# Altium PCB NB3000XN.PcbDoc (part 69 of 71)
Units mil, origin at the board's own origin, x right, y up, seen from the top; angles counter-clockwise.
Board outline 9527.56 x 6929.77 mil, 6 copper layers (Top Layer, GND+SHIELD, MidLayer1, MidLayer2, P2 - 3V3+5V0, Bottom Layer), stack 62.375 mil thick; 832 components, 1027 nets, 4655 pads, 4981 vias.
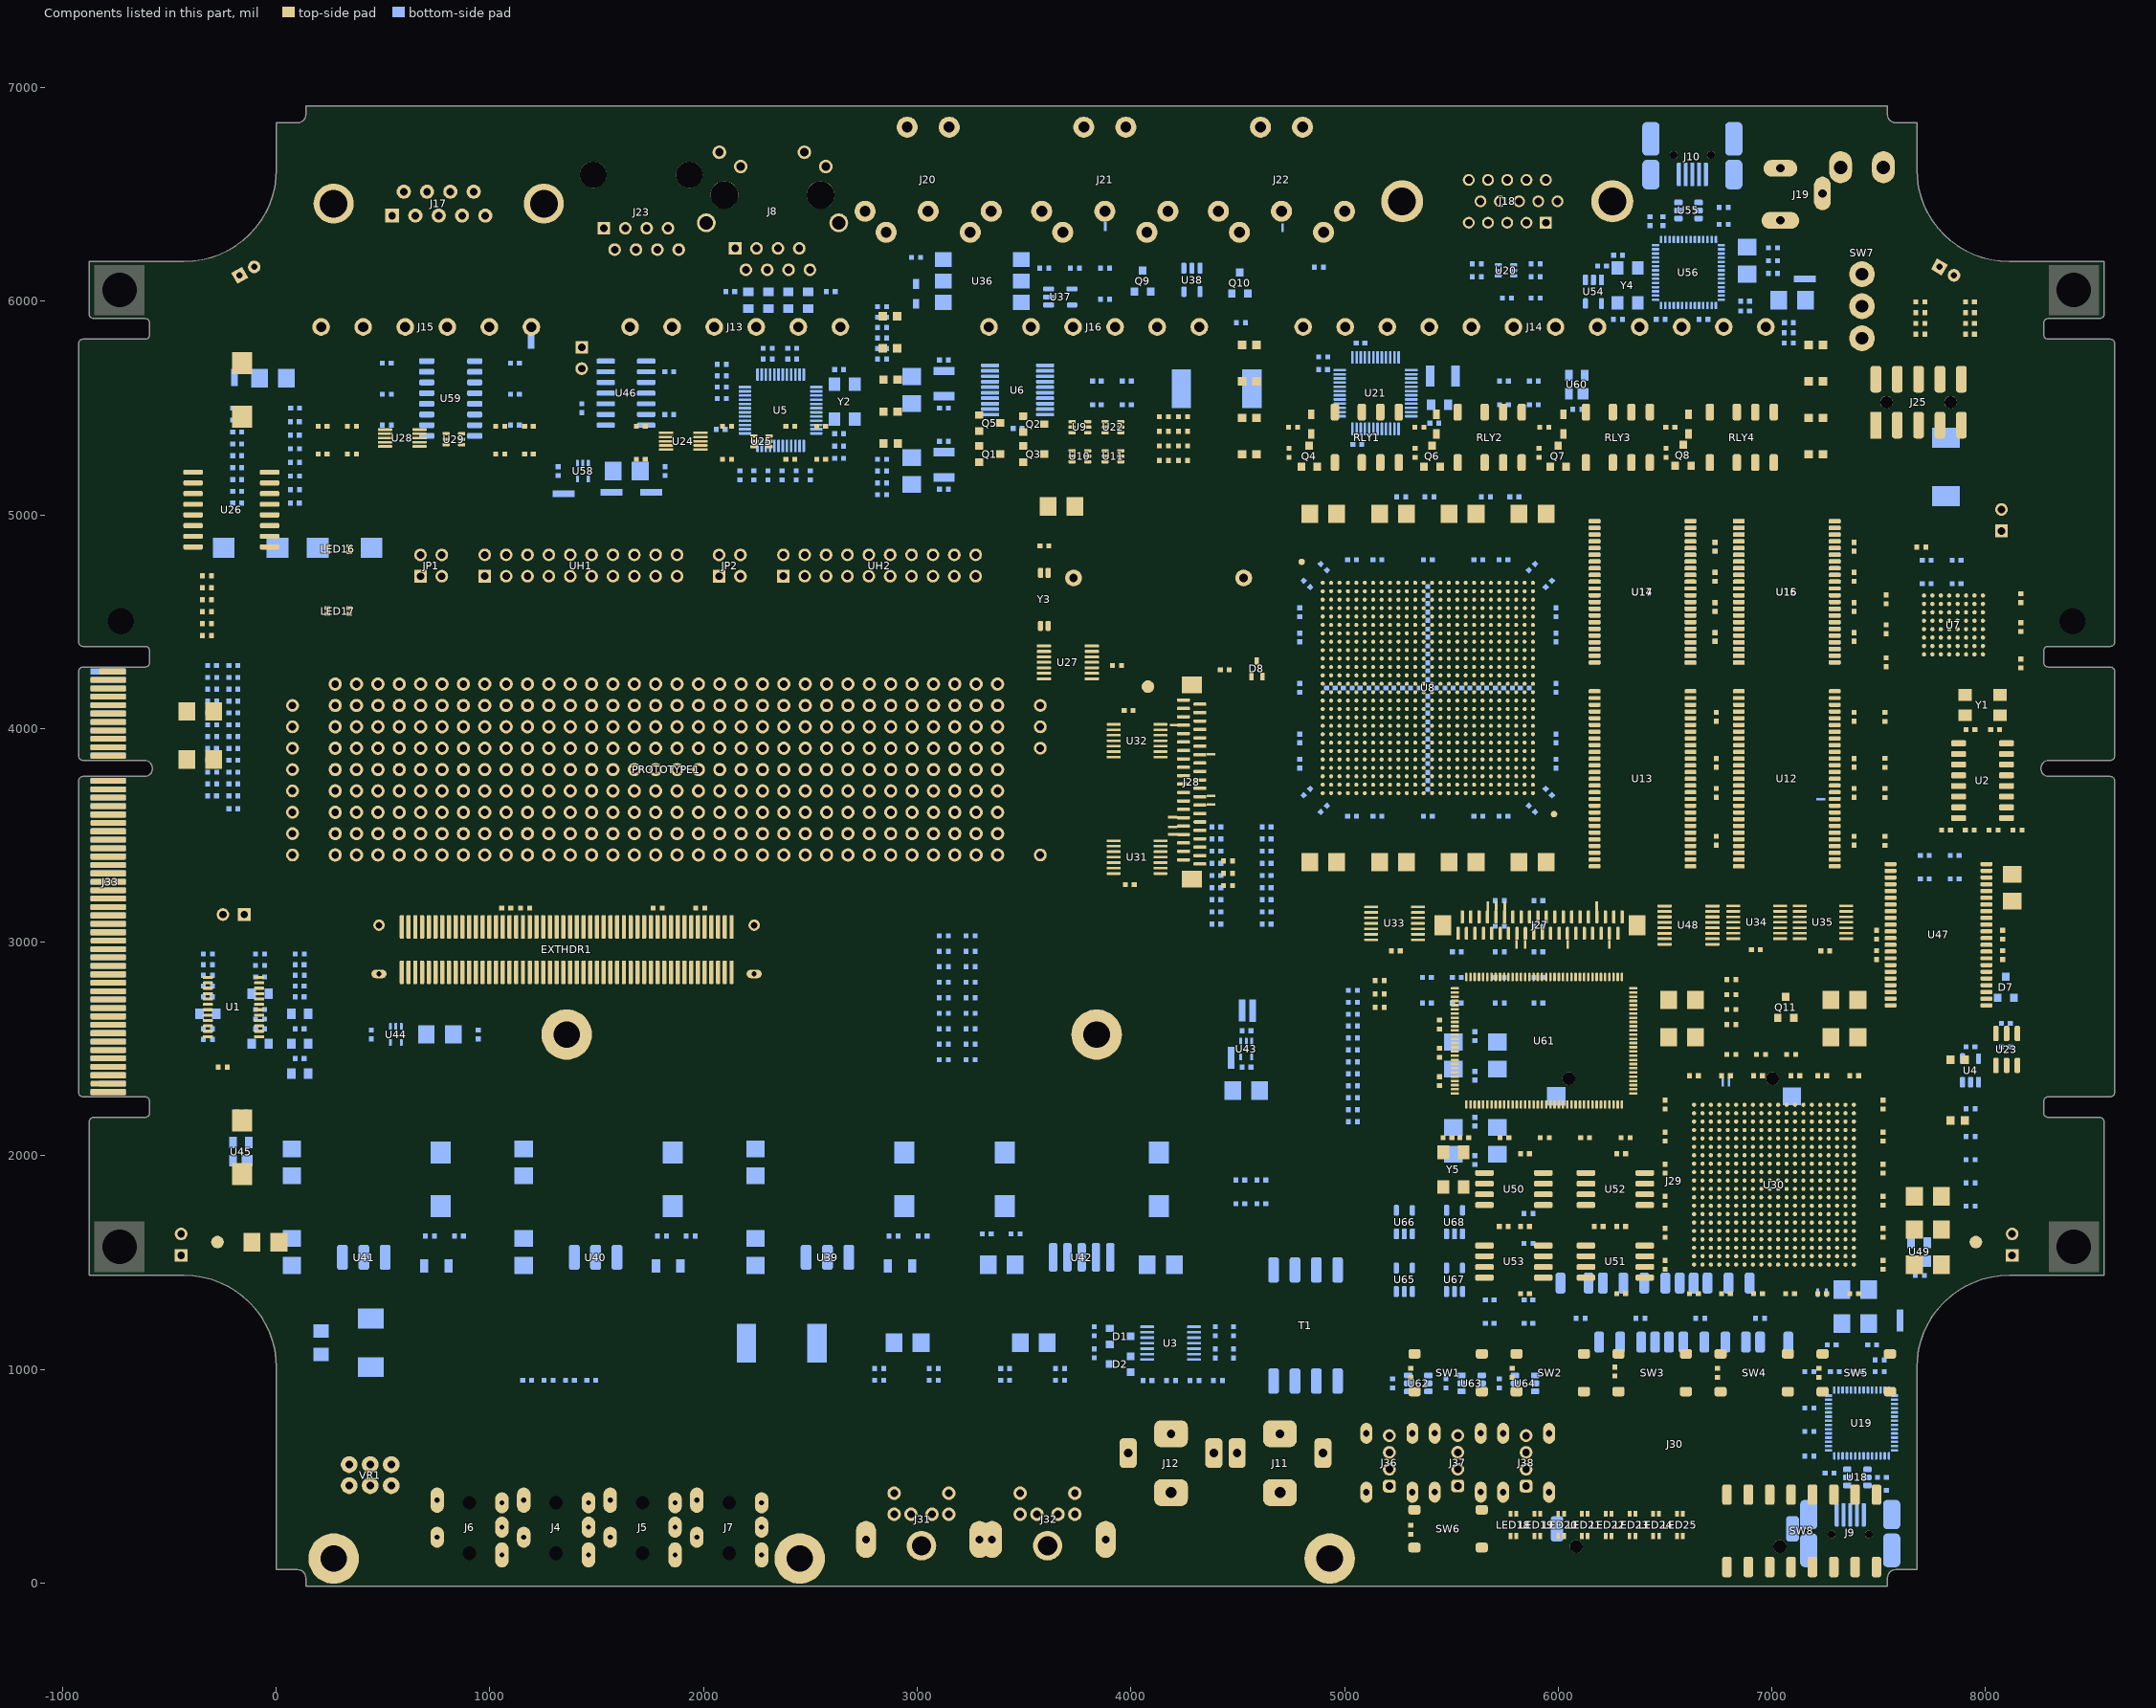
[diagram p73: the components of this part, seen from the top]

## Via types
v1: diameter 23, hole 11.81, Top Layer to Bottom Layer, 3672 vias
v2: diameter 26, hole 11.81, Top Layer to Bottom Layer, 461 vias
v3: diameter 19, hole 11.81, Top Layer to Bottom Layer, tented both sides, 396 vias
v4: diameter 23.62, hole 11.81, Top Layer to Bottom Layer, 288 vias
v5: diameter 20, hole 11.81, Top Layer to Bottom Layer, 91 vias
v6: diameter 23, hole 11.81, Top Layer to Bottom Layer, tented both sides, 50 vias
v7: diameter 31, hole 11.81, Top Layer to Bottom Layer, 15 vias
v8: diameter 27.56, hole 11.81, Top Layer to Bottom Layer, tented both sides, 4 vias
v9: diameter 29, hole 11.81, Top Layer to Bottom Layer, 3 vias
v10: diameter 21, hole 11.81, Top Layer to Bottom Layer, 1 vias

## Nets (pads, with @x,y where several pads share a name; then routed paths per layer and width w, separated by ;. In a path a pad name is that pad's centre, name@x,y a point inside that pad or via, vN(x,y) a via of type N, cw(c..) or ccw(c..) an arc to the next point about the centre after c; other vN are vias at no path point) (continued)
copper on no net: (continued)
  Top Layer w8: v2(6773.78,1550.04) 6793.46,1569.72 ; v2@6773.78,1559.04 ccw(c6773.78,1580.77) 6789.14,1565.4 ccw(c6804.51,1550.04) v2@6782.78,1550.04 ; v2(6773.78,1825.63) 6793.46,1845.31 ; v2@6773.78,1834.63 ccw(c6773.78,1856.36) 6789.14,1840.99 ccw(c6804.51,1825.63) v2@6782.78,1825.63 ; 6787.62,1569.72 cw(c6773.52,1569.72) 6783.49,1559.75 cw(c6793.46,1549.78) 6793.46,1563.88 ; 6787.62,1845.31 cw(c6773.52,1845.31) 6783.49,1835.34 cw(c6793.46,1825.37) 6793.46,1839.47 ; v2(6813.15,1471.3) 6832.83,1490.98 ; v2@6813.15,1480.3 ccw(c6813.15,1502.03) 6828.51,1486.66 ccw(c6843.88,1471.3) v2@6822.15,1471.3 ; v2(6813.15,1510.67) 6832.83,1530.35 ; v2@6813.15,1519.67 ccw(c6813.15,1541.4) 6828.51,1526.03 ccw(c6843.88,1510.67) v2@6822.15,1510.67 ; v2(6813.15,1550.04) 6832.83,1569.72 ; v2@6813.15,1559.04 ccw(c6813.15,1580.77) 6828.51,1565.4 ccw(c6843.88,1550.04) v2@6822.15,1550.04 ; v2(6813.15,1589.41) 6832.83,1609.09 ; v2@6813.15,1598.41 ccw(c6813.15,1620.14) 6828.51,1604.77 ccw(c6843.88,1589.41) v2@6822.15,1589.41 ; v2(6813.15,1628.78) 6832.83,1648.46 ; v2@6813.15,1637.78 ccw(c6813.15,1659.51) 6828.51,1644.14 ccw(c6843.88,1628.78) v2@6822.15,1628.78 ; v2(6813.15,1707.52) 6832.83,1727.2 ; v2@6813.15,1716.52 ccw(c6813.15,1738.25) 6828.51,1722.88 ccw(c6843.88,1707.52) v2@6822.15,1707.52 ; v2@6813.15,1895.37 cw(c6813.15,1873.64) 6828.51,1889.01 cw(c6843.88,1904.37) v2@6822.15,1904.37 ; v2(6813.15,1904.37) 6832.83,1884.68 ; v2@6813.15,1974.11 cw(c6813.15,1952.38) 6828.51,1967.75 cw(c6843.88,1983.11) v2@6822.15,1983.11 ; v2(6813.15,1983.11) 6832.83,1963.43 ; 6826.99,1490.98 cw(c6812.89,1490.98) 6822.86,1481.01 cw(c6832.83,1471.04) 6832.83,1485.14 ; 6826.99,1530.35 cw(c6812.89,1530.35) 6822.86,1520.38 cw(c6832.83,1510.41) 6832.83,1524.51 ; 6826.99,1569.72 cw(c6812.89,1569.72) 6822.86,1559.75 cw(c6832.83,1549.78) 6832.83,1563.88 ; 6826.99,1609.09 cw(c6812.89,1609.09) 6822.86,1599.12 cw(c6832.83,1589.15) 6832.83,1603.25 ; 6826.99,1648.46 cw(c6812.89,1648.46) 6822.86,1638.49 cw(c6832.83,1628.52) 6832.83,1642.62 ; 6826.99,1727.2 cw(c6812.89,1727.2) 6822.86,1717.23 cw(c6832.83,1707.26) 6832.83,1721.36 ; 6826.99,1884.68 ccw(c6812.89,1884.68) 6822.86,1894.66 ccw(c6832.83,1904.63) 6832.83,1890.53 ; 6826.99,1963.43 ccw(c6812.89,1963.43) 6822.86,1973.4 ccw(c6832.83,1983.37) 6832.83,1969.27 ; v2(6852.52,1550.04) 6872.2,1569.72 ; v2@6852.52,1559.04 ccw(c6852.52,1580.77) 6867.88,1565.4 ccw(c6883.25,1550.04) v2@6861.52,1550.04 ; v2(6852.52,1589.41) 6872.2,1609.09 ; v2@6852.52,1598.41 ccw(c6852.52,1620.14) 6867.88,1604.77 ccw(c6883.25,1589.41) v2@6861.52,1589.41 ; v2(6852.52,1628.78) 6872.2,1648.46 ; v2@6852.52,1637.78 ccw(c6852.52,1659.51) 6867.88,1644.14 ccw(c6883.25,1628.78) v2@6861.52,1628.78 ; v2(6852.52,1668.15) 6872.2,1687.83 ; v2@6852.52,1677.15 ccw(c6852.52,1698.88) 6867.88,1683.51 ccw(c6883.25,1668.15) v2@6861.52,1668.15 ; v2(6852.52,1707.52) 6872.2,1727.2 ; v2@6852.52,1716.52 ccw(c6852.52,1738.25) 6867.88,1722.88 ccw(c6883.25,1707.52) v2@6861.52,1707.52 ; v2(6852.52,1746.89) 6872.2,1766.57 ; v2@6852.52,1755.89 ccw(c6852.52,1777.62) 6867.88,1762.25 ccw(c6883.25,1746.89) v2@6861.52,1746.89 ; v2(6852.52,1786.26) 6872.2,1805.94 ; v2@6852.52,1795.26 ccw(c6852.52,1816.99) 6867.88,1801.62 ccw(c6883.25,1786.26) v2@6861.52,1786.26 ; v2(6852.52,1825.63) 6872.2,1845.31 ; v2@6852.52,1834.63 ccw(c6852.52,1856.36) 6867.88,1840.99 ccw(c6883.25,1825.63) v2@6861.52,1825.63 ; v2@6852.52,1895.37 cw(c6852.52,1873.64) 6867.88,1889.01 cw(c6883.25,1904.37) v2@6861.52,1904.37 ; v2(6852.52,1904.37) 6872.2,1884.68 ; v2@6852.52,1934.74 cw(c6852.52,1913.01) 6867.88,1928.38 cw(c6883.25,1943.74) v2@6861.52,1943.74 ; v2(6852.52,1943.74) 6872.2,1924.06 ; v2@6852.52,1974.11 cw(c6852.52,1952.38) 6867.88,1967.75 cw(c6883.25,1983.11) v2@6861.52,1983.11 ; v2(6852.52,1983.11) 6872.2,1963.43 ; v2@6852.52,2013.48 cw(c6852.52,1991.75) 6867.88,2007.12 cw(c6883.25,2022.48) v2@6861.52,2022.48 ; v2(6852.52,2022.48) 6872.2,2002.8 ; v2@6852.52,2052.85 cw(c6852.52,2031.12) 6867.88,2046.49 cw(c6883.25,2061.85) v2@6861.52,2061.85 ; v2(6852.52,2061.85) 6872.2,2042.17 ; v2@6852.52,2092.22 cw(c6852.52,2070.49) 6867.88,2085.86 cw(c6883.25,2101.22) v2@6861.52,2101.22 ; v2(6852.52,2101.22) 6872.2,2081.54 ; 6866.36,1569.72 cw(c6852.26,1569.72) 6862.23,1559.75 cw(c6872.2,1549.78) 6872.2,1563.88 ; 6866.36,1609.09 cw(c6852.26,1609.09) 6862.23,1599.12 cw(c6872.2,1589.15) 6872.2,1603.25 ; 6866.36,1648.46 cw(c6852.26,1648.46) 6862.23,1638.49 cw(c6872.2,1628.52) 6872.2,1642.62 ; 6866.36,1687.83 cw(c6852.26,1687.83) 6862.23,1677.86 cw(c6872.2,1667.89) 6872.2,1681.99 ; 6866.36,1727.2 cw(c6852.26,1727.2) 6862.23,1717.23 cw(c6872.2,1707.26) 6872.2,1721.36 ; 6866.36,1766.57 cw(c6852.26,1766.57) 6862.23,1756.6 cw(c6872.2,1746.63) 6872.2,1760.73 ; 6866.36,1805.94 cw(c6852.26,1805.94) 6862.23,1795.97 cw(c6872.2,1786) 6872.2,1800.1 ; 6866.36,1845.31 cw(c6852.26,1845.31) 6862.23,1835.34 cw(c6872.2,1825.37) 6872.2,1839.47 ; 6866.36,1884.68 ccw(c6852.26,1884.68) 6862.23,1894.66 ccw(c6872.2,1904.63) 6872.2,1890.53 ; 6866.36,1924.06 ccw(c6852.26,1924.06) 6862.23,1934.03 ccw(c6872.2,1944) 6872.2,1929.9 ; 6866.36,1963.43 ccw(c6852.26,1963.43) 6862.23,1973.4 ccw(c6872.2,1983.37) 6872.2,1969.27 ; 6866.36,2002.8 ccw(c6852.26,2002.8) 6862.23,2012.77 ccw(c6872.2,2022.74) 6872.2,2008.64 ; 6866.36,2042.17 ccw(c6852.26,2042.17) 6862.23,2052.14 ccw(c6872.2,2062.11) 6872.2,2048.01 ; 6866.36,2081.54 ccw(c6852.26,2081.54) 6862.23,2091.51 ccw(c6872.2,2101.48) 6872.2,2087.38 ; v2(6891.89,1510.67) 6911.57,1530.35 ; v2@6891.89,1519.67 ccw(c6891.89,1541.4) 6907.25,1526.03 ccw(c6922.62,1510.67) v2@6900.89,1510.67 ; v2(6891.89,1550.04) 6911.57,1569.72 ; v2@6891.89,1559.04 ccw(c6891.89,1580.77) 6907.25,1565.4 ccw(c6922.62,1550.04) v2@6900.89,1550.04 ; v2(6891.89,1589.41) 6911.57,1609.09 ; v2@6891.89,1598.41 ccw(c6891.89,1620.14) 6907.25,1604.77 ccw(c6922.62,1589.41) v2@6900.89,1589.41 ; v2(6891.89,1668.15) 6911.57,1687.83 ; v2@6891.89,1677.15 ccw(c6891.89,1698.88) 6907.25,1683.51 ccw(c6922.62,1668.15) v2@6900.89,1668.15 ; v2(6891.89,1707.52) 6911.57,1727.2 ; v2@6891.89,1716.52 ccw(c6891.89,1738.25) 6907.25,1722.88 ccw(c6922.62,1707.52) v2@6900.89,1707.52 ; v2(6891.89,1786.26) 6911.57,1805.94 ; v2@6891.89,1795.26 ccw(c6891.89,1816.99) 6907.25,1801.62 ccw(c6922.62,1786.26) v2@6900.89,1786.26 ; v2@6891.89,1934.74 cw(c6891.89,1913.01) 6907.25,1928.38 cw(c6922.62,1943.74) v2@6900.89,1943.74 ; v2(6891.89,1943.74) 6911.57,1924.06 ; v2@6891.89,2013.48 cw(c6891.89,1991.75) 6907.25,2007.12 cw(c6922.62,2022.48) v2@6900.89,2022.48 ; v2(6891.89,2022.48) 6911.57,2002.8 ; v2@6891.89,2052.85 cw(c6891.89,2031.12) 6907.25,2046.49 cw(c6922.62,2061.85) v2@6900.89,2061.85 ; v2(6891.89,2061.85) 6911.57,2042.17 ; 6905.73,1530.35 cw(c6891.63,1530.35) 6901.6,1520.38 cw(c6911.57,1510.41) 6911.57,1524.51 ; 6905.73,1569.72 cw(c6891.63,1569.72) 6901.6,1559.75 cw(c6911.57,1549.78) 6911.57,1563.88 ; 6905.73,1609.09 cw(c6891.63,1609.09) 6901.6,1599.12 cw(c6911.57,1589.15) 6911.57,1603.25 ; 6905.73,1687.83 cw(c6891.63,1687.83) 6901.6,1677.86 cw(c6911.57,1667.89) 6911.57,1681.99 ; 6905.73,1727.2 cw(c6891.63,1727.2) 6901.6,1717.23 cw(c6911.57,1707.26) 6911.57,1721.36 ; 6905.73,1805.94 cw(c6891.63,1805.94) 6901.6,1795.97 cw(c6911.57,1786) 6911.57,1800.1 ; 6905.73,1924.06 ccw(c6891.63,1924.06) 6901.6,1934.03 ccw(c6911.57,1944) 6911.57,1929.9 ; 6905.73,2002.8 ccw(c6891.63,2002.8) 6901.6,2012.77 ccw(c6911.57,2022.74) 6911.57,2008.64 ; 6905.73,2042.17 ccw(c6891.63,2042.17) 6901.6,2052.14 ccw(c6911.57,2062.11) 6911.57,2048.01 ; v2(6931.26,1471.3) 6950.94,1490.98 ; v2@6931.26,1480.3 ccw(c6931.26,1502.03) 6946.62,1486.66 ccw(c6961.99,1471.3) v2@6940.26,1471.3 ; v2(6931.26,1510.67) 6950.94,1530.35 ; v2@6931.26,1519.67 ccw(c6931.26,1541.4) 6946.62,1526.03 ccw(c6961.99,1510.67) v2@6940.26,1510.67 ; v2(6931.26,1550.04) 6950.94,1569.72 ; v2@6931.26,1559.04 ccw(c6931.26,1580.77) 6946.62,1565.4 ccw(c6961.99,1550.04) v2@6940.26,1550.04 ; v2(6931.26,1589.41) 6950.94,1609.09 ; v2@6931.26,1598.41 ccw(c6931.26,1620.14) 6946.62,1604.77 ccw(c6961.99,1589.41) v2@6940.26,1589.41 ; v2(6931.26,1628.78) 6950.94,1648.46 ; v2@6931.26,1637.78 ccw(c6931.26,1659.51) 6946.62,1644.14 ccw(c6961.99,1628.78) v2@6940.26,1628.78 ; v2(6931.26,1668.15) 6950.94,1687.83 ; v2@6931.26,1677.15 ccw(c6931.26,1698.88) 6946.62,1683.51 ccw(c6961.99,1668.15) v2@6940.26,1668.15 ; v2(6931.26,1707.52) 6950.94,1727.2 ; v2@6931.26,1716.52 ccw(c6931.26,1738.25) 6946.62,1722.88 ccw(c6961.99,1707.52) v2@6940.26,1707.52 ; v2(6931.26,1746.89) 6950.94,1766.57 ; v2@6931.26,1755.89 ccw(c6931.26,1777.62) 6946.62,1762.25 ccw(c6961.99,1746.89) v2@6940.26,1746.89 ; v2@6931.26,1974.11 cw(c6931.26,1952.38) 6946.62,1967.75 cw(c6961.99,1983.11) v2@6940.26,1983.11 ; v2(6931.26,1983.11) 6950.94,1963.43 ; v2@6931.26,2013.48 cw(c6931.26,1991.75) 6946.62,2007.12 cw(c6961.99,2022.48) v2@6940.26,2022.48 ; v2(6931.26,2022.48) 6950.94,2002.8 ; v2@6931.26,2052.85 cw(c6931.26,2031.12) 6946.62,2046.49 cw(c6961.99,2061.85) v2@6940.26,2061.85 ; v2(6931.26,2061.85) 6950.94,2042.17 ; 6945.1,1490.98 cw(c6931,1490.98) 6940.97,1481.01 cw(c6950.94,1471.04) 6950.94,1485.14 ; 6945.1,1530.35 cw(c6931,1530.35) 6940.97,1520.38 cw(c6950.94,1510.41) 6950.94,1524.51 ; 6945.1,1569.72 cw(c6931,1569.72) 6940.97,1559.75 cw(c6950.94,1549.78) 6950.94,1563.88 ; 6945.1,1609.09 cw(c6931,1609.09) 6940.97,1599.12 cw(c6950.94,1589.15) 6950.94,1603.25 ; 6945.1,1648.46 cw(c6931,1648.46) 6940.97,1638.49 cw(c6950.94,1628.52) 6950.94,1642.62 ; 6945.1,1687.83 cw(c6931,1687.83) 6940.97,1677.86 cw(c6950.94,1667.89) 6950.94,1681.99 ; 6945.1,1727.2 cw(c6931,1727.2) 6940.97,1717.23 cw(c6950.94,1707.26) 6950.94,1721.36 ; 6945.1,1766.57 cw(c6931,1766.57) 6940.97,1756.6 cw(c6950.94,1746.63) 6950.94,1760.73 ; 6945.1,1963.43 ccw(c6931,1963.43) 6940.97,1973.4 ccw(c6950.94,1983.37) 6950.94,1969.27 ; 6945.1,2002.8 ccw(c6931,2002.8) 6940.97,2012.77 ccw(c6950.94,2022.74) 6950.94,2008.64 ; 6945.1,2042.17 ccw(c6931,2042.17) 6940.97,2052.14 ccw(c6950.94,2062.11) 6950.94,2048.01 ; v2(6970.63,1510.67) 6990.31,1530.35 ; v2@6970.63,1519.67 ccw(c6970.63,1541.4) 6985.99,1526.03 ccw(c7001.36,1510.67) v2@6979.63,1510.67 ; v2(6970.63,1550.04) 6990.31,1569.72 ; v2@6970.63,1559.04 ccw(c6970.63,1580.77) 6985.99,1565.4 ccw(c7001.36,1550.04) v2@6979.63,1550.04 ; v2(6970.63,1589.41) 6990.31,1609.09 ; v2@6970.63,1598.41 ccw(c6970.63,1620.14) 6985.99,1604.77 ccw(c7001.36,1589.41) v2@6979.63,1589.41 ; v2(6970.63,1628.78) 6990.31,1648.46 ; v2@6970.63,1637.78 ccw(c6970.63,1659.51) 6985.99,1644.14 ccw(c7001.36,1628.78) v2@6979.63,1628.78 ; v2(6970.63,1668.15) 6990.31,1687.83 ; v2@6970.63,1677.15 ccw(c6970.63,1698.88) 6985.99,1683.51 ccw(c7001.36,1668.15) v2@6979.63,1668.15 ; v2(6970.63,1707.52) 6990.31,1727.2 ; v2@6970.63,1716.52 ccw(c6970.63,1738.25) 6985.99,1722.88 ccw(c7001.36,1707.52) v2@6979.63,1707.52 ; v2(6970.63,1746.89) 6990.31,1766.57 ; v2@6970.63,1755.89 ccw(c6970.63,1777.62) 6985.99,1762.25 ccw(c7001.36,1746.89) v2@6979.63,1746.89 ; v2@6970.63,2013.48 cw(c6970.63,1991.75) 6985.99,2007.12 cw(c7001.36,2022.48) v2@6979.63,2022.48 ; v2(6970.63,2022.48) 6990.31,2002.8 ; v2@6970.63,2052.85 cw(c6970.63,2031.12) 6985.99,2046.49 cw(c7001.36,2061.85) v2@6979.63,2061.85 ; v2(6970.63,2061.85) 6990.31,2042.17 ; 6984.47,1530.35 cw(c6970.37,1530.35) 6980.34,1520.38 cw(c6990.31,1510.41) 6990.31,1524.51 ; 6984.47,1569.72 cw(c6970.37,1569.72) 6980.34,1559.75 cw(c6990.31,1549.78) 6990.31,1563.88 ; 6984.47,1609.09 cw(c6970.37,1609.09) 6980.34,1599.12 cw(c6990.31,1589.15) 6990.31,1603.25 ; 6984.47,1648.46 cw(c6970.37,1648.46) 6980.34,1638.49 cw(c6990.31,1628.52) 6990.31,1642.62 ; 6984.47,1687.83 cw(c6970.37,1687.83) 6980.34,1677.86 cw(c6990.31,1667.89) 6990.31,1681.99 ; 6984.47,1727.2 cw(c6970.37,1727.2) 6980.34,1717.23 cw(c6990.31,1707.26) 6990.31,1721.36 ; 6984.47,1766.57 cw(c6970.37,1766.57) 6980.34,1756.6 cw(c6990.31,1746.63) 6990.31,1760.73 ; 6984.47,2002.8 ccw(c6970.37,2002.8) 6980.34,2012.77 ccw(c6990.31,2022.74) 6990.31,2008.64 ; 6984.47,2042.17 ccw(c6970.37,2042.17) 6980.34,2052.14 ccw(c6990.31,2062.11) 6990.31,2048.01 ; 7029.69,1485.14 cw(c7029.69,1471.04) 7039.66,1481.01 cw(c7049.63,1490.98) 7035.53,1490.98 ; 7029.69,1490.98 v2(7049.37,1471.3) ; 7029.69,1563.88 cw(c7029.69,1549.78) 7039.66,1559.75 cw(c7049.63,1569.72) 7035.53,1569.72 ; 7029.69,1569.72 v2(7049.37,1550.04) ; 7029.69,1642.62 cw(c7029.69,1628.52) 7039.66,1638.49 cw(c7049.63,1648.46) 7035.53,1648.46 ; 7029.69,1648.46 v2(7049.37,1628.78) ; 7029.69,1681.99 cw(c7029.69,1667.89) 7039.66,1677.86 cw(c7049.63,1687.83) 7035.53,1687.83 ; 7029.69,1687.83 v2(7049.37,1668.15) ; 7029.69,1721.36 cw(c7029.69,1707.26) 7039.66,1717.23 cw(c7049.63,1727.2) 7035.53,1727.2 ; 7029.69,1727.2 v2(7049.37,1707.52) ; 7029.69,1963.43 v2(7049.37,1983.11) ; 7029.69,1969.27 ccw(c7029.69,1983.37) 7039.66,1973.4 ccw(c7049.63,1963.43) 7035.53,1963.43 ; 7029.69,2002.8 v2(7049.37,2022.48) ; 7029.69,2008.64 ccw(c7029.69,2022.74) 7039.66,2012.77 ccw(c7049.63,2002.8) 7035.53,2002.8 ; 7029.69,2042.17 v2(7049.37,2061.85) ; 7029.69,2048.01 ccw(c7029.69,2062.11) 7039.66,2052.14 ccw(c7049.63,2042.17) 7035.53,2042.17 ; 7029.69,2081.54 v2(7049.37,2101.22) ; 7029.69,2087.38 ccw(c7029.69,2101.48) 7039.66,2091.51 ccw(c7049.63,2081.54) 7035.53,2081.54 ; v2@7040.37,1471.3 ccw(c7018.64,1471.3) 7034.01,1486.66 ccw(c7049.37,1502.03) v2@7049.37,1480.3 ; v2@7040.37,1550.04 ccw(c7018.64,1550.04) 7034.01,1565.4 ccw(c7049.37,1580.77) v2@7049.37,1559.04 ; v2@7040.37,1628.78 ccw(c7018.64,1628.78) 7034.01,1644.14 ccw(c7049.37,1659.51) v2@7049.37,1637.78 ; v2@7040.37,1668.15 ccw(c7018.64,1668.15) 7034.01,1683.51 ccw(c7049.37,1698.88) v2@7049.37,1677.15 ; v2@7040.37,1707.52 ccw(c7018.64,1707.52) 7034.01,1722.88 ccw(c7049.37,1738.25) v2@7049.37,1716.52 ; v2@7040.37,1983.11 cw(c7018.64,1983.11) 7034.01,1967.75 cw(c7049.37,1952.38) v2@7049.37,1974.11 ; v2@7040.37,2022.48 cw(c7018.64,2022.48) 7034.01,2007.12 cw(c7049.37,1991.75) v2@7049.37,2013.48 ; v2@7040.37,2061.85 cw(c7018.64,2061.85) 7034.01,2046.49 cw(c7049.37,2031.12) v2@7049.37,2052.85 ; v2@7040.37,2101.22 cw(c7018.64,2101.22) 7034.01,2085.86 cw(c7049.37,2070.49) v2@7049.37,2092.22 ; 7069.06,1485.14 cw(c7069.06,1471.04) 7079.03,1481.01 cw(c7089,1490.98) 7074.9,1490.98 ; 7069.06,1490.98 v2(7088.74,1471.3) ; 7069.06,1524.51 cw(c7069.06,1510.41) 7079.03,1520.38 cw(c7089,1530.35) 7074.9,1530.35 ; 7069.06,1530.35 v2(7088.74,1510.67) ; 7069.06,1563.88 cw(c7069.06,1549.78) 7079.03,1559.75 cw(c7089,1569.72) 7074.9,1569.72 ; 7069.06,1569.72 v2(7088.74,1550.04) ; 7069.06,1603.25 cw(c7069.06,1589.15) 7079.03,1599.12 cw(c7089,1609.09) 7074.9,1609.09 ; 7069.06,1609.09 v2(7088.74,1589.41) ; 7069.06,1642.62 cw(c7069.06,1628.52) 7079.03,1638.49 cw(c7089,1648.46) 7074.9,1648.46 ; 7069.06,1648.46 v2(7088.74,1628.78) ; 7069.06,1681.99 cw(c7069.06,1667.89) 7079.03,1677.86 cw(c7089,1687.83) 7074.9,1687.83 ; 7069.06,1687.83 v2(7088.74,1668.15) ; 7069.06,1721.36 cw(c7069.06,1707.26) 7079.03,1717.23 cw(c7089,1727.2) 7074.9,1727.2 ; 7069.06,1727.2 v2(7088.74,1707.52) ; 7069.06,1760.73 cw(c7069.06,1746.63) 7079.03,1756.6 cw(c7089,1766.57) 7074.9,1766.57 ; 7069.06,1766.57 v2(7088.74,1746.89) ; 7069.06,1963.43 v2(7088.74,1983.11) ; 7069.06,1969.27 ccw(c7069.06,1983.37) 7079.03,1973.4 ccw(c7089,1963.43) 7074.9,1963.43 ; 7069.06,2002.8 v2(7088.74,2022.48) ; 7069.06,2008.64 ccw(c7069.06,2022.74) 7079.03,2012.77 ccw(c7089,2002.8) 7074.9,2002.8 ; v2@7079.74,1471.3 ccw(c7058.01,1471.3) 7073.38,1486.66 ccw(c7088.74,1502.03) v2@7088.74,1480.3 ; v2@7079.74,1510.67 ccw(c7058.01,1510.67) 7073.38,1526.03 ccw(c7088.74,1541.4) v2@7088.74,1519.67 ; v2@7079.74,1550.04 ccw(c7058.01,1550.04) 7073.38,1565.4 ccw(c7088.74,1580.77) v2@7088.74,1559.04 ; v2@7079.74,1589.41 ccw(c7058.01,1589.41) 7073.38,1604.77 ccw(c7088.74,1620.14) v2@7088.74,1598.41 ; v2@7079.74,1628.78 ccw(c7058.01,1628.78) 7073.38,1644.14 ccw(c7088.74,1659.51) v2@7088.74,1637.78 ; v2@7079.74,1668.15 ccw(c7058.01,1668.15) 7073.38,1683.51 ccw(c7088.74,1698.88) v2@7088.74,1677.15 ; v2@7079.74,1707.52 ccw(c7058.01,1707.52) 7073.38,1722.88 ccw(c7088.74,1738.25) v2@7088.74,1716.52 ; v2@7079.74,1746.89 ccw(c7058.01,1746.89) 7073.38,1762.25 ccw(c7088.74,1777.62) v2@7088.74,1755.89 ; v2@7079.74,1983.11 cw(c7058.01,1983.11) 7073.38,1967.75 cw(c7088.74,1952.38) v2@7088.74,1974.11 ; v2@7079.74,2022.48 cw(c7058.01,2022.48) 7073.38,2007.12 cw(c7088.74,1991.75) v2@7088.74,2013.48 ; 7108.43,1485.14 cw(c7108.43,1471.04) 7118.4,1481.01 cw(c7128.37,1490.98) 7114.27,1490.98 ; 7108.43,1490.98 v2(7128.11,1471.3) ; 7108.43,1524.51 cw(c7108.43,1510.41) 7118.4,1520.38 cw(c7128.37,1530.35) 7114.27,1530.35 ; 7108.43,1530.35 v2(7128.11,1510.67) ; 7108.43,1563.88 cw(c7108.43,1549.78) 7118.4,1559.75 cw(c7128.37,1569.72) 7114.27,1569.72 ; 7108.43,1569.72 v2(7128.11,1550.04) ; 7108.43,1603.25 cw(c7108.43,1589.15) 7118.4,1599.12 cw(c7128.37,1609.09) 7114.27,1609.09 ; 7108.43,1609.09 v2(7128.11,1589.41) ; 7108.43,1681.99 cw(c7108.43,1667.89) 7118.4,1677.86 cw(c7128.37,1687.83) 7114.27,1687.83 ; 7108.43,1687.83 v2(7128.11,1668.15) ; 7108.43,1721.36 cw(c7108.43,1707.26) 7118.4,1717.23 cw(c7128.37,1727.2) 7114.27,1727.2 ; 7108.43,1727.2 v2(7128.11,1707.52) ; 7108.43,1800.1 cw(c7108.43,1786) 7118.4,1795.97 cw(c7128.37,1805.94) 7114.27,1805.94 ; 7108.43,1805.94 v2(7128.11,1786.26) ; 7108.43,1839.47 cw(c7108.43,1825.37) 7118.4,1835.34 cw(c7128.37,1845.31) 7114.27,1845.31 ; 7108.43,1845.31 v2(7128.11,1825.63) ; 7108.43,1884.68 v2(7128.11,1904.37) ; 7108.43,1890.53 ccw(c7108.43,1904.63) 7118.4,1894.66 ccw(c7128.37,1884.68) 7114.27,1884.68 ; 7108.43,1924.06 v2(7128.11,1943.74) ; 7108.43,1929.9 ccw(c7108.43,1944) 7118.4,1934.03 ccw(c7128.37,1924.06) 7114.27,1924.06 ; 7108.43,2002.8 v2(7128.11,2022.48) ; 7108.43,2008.64 ccw(c7108.43,2022.74) 7118.4,2012.77 ccw(c7128.37,2002.8) 7114.27,2002.8 ; v2@7119.11,1471.3 ccw(c7097.38,1471.3) 7112.75,1486.66 ccw(c7128.11,1502.03) v2@7128.11,1480.3 ; v2@7119.11,1510.67 ccw(c7097.38,1510.67) 7112.75,1526.03 ccw(c7128.11,1541.4) v2@7128.11,1519.67 ; v2@7119.11,1550.04 ccw(c7097.38,1550.04) 7112.75,1565.4 ccw(c7128.11,1580.77) v2@7128.11,1559.04 ; v2@7119.11,1589.41 ccw(c7097.38,1589.41) 7112.75,1604.77 ccw(c7128.11,1620.14) v2@7128.11,1598.41 ; v2@7119.11,1668.15 ccw(c7097.38,1668.15) 7112.75,1683.51 ccw(c7128.11,1698.88) v2@7128.11,1677.15 ; v2@7119.11,1707.52 ccw(c7097.38,1707.52) 7112.75,1722.88 ccw(c7128.11,1738.25) v2@7128.11,1716.52 ; v2@7119.11,1786.26 ccw(c7097.38,1786.26) 7112.75,1801.62 ccw(c7128.11,1816.99) v2@7128.11,1795.26 ; v2@7119.11,1825.63 ccw(c7097.38,1825.63) 7112.75,1840.99 ccw(c7128.11,1856.36) v2@7128.11,1834.63 ; v2@7119.11,1904.37 cw(c7097.38,1904.37) 7112.75,1889.01 cw(c7128.11,1873.64) v2@7128.11,1895.37 ; v2@7119.11,1943.74 cw(c7097.38,1943.74) 7112.75,1928.38 cw(c7128.11,1913.01) v2@7128.11,1934.74 ; v2@7119.11,2022.48 cw(c7097.38,2022.48) 7112.75,2007.12 cw(c7128.11,1991.75) v2@7128.11,2013.48 ; 7147.8,1485.14 cw(c7147.8,1471.04) 7157.77,1481.01 cw(c7167.74,1490.98) 7153.64,1490.98 ; 7147.8,1490.98 v2(7167.48,1471.3) ; 7147.8,1563.88 cw(c7147.8,1549.78) 7157.77,1559.75 cw(c7167.74,1569.72) 7153.64,1569.72 ; 7147.8,1569.72 v2(7167.48,1550.04) ; 7147.8,1603.25 cw(c7147.8,1589.15) 7157.77,1599.12 cw(c7167.74,1609.09) 7153.64,1609.09 ; 7147.8,1609.09 v2(7167.48,1589.41) ; 7147.8,1642.62 cw(c7147.8,1628.52) 7157.77,1638.49 cw(c7167.74,1648.46) 7153.64,1648.46 ; 7147.8,1648.46 v2(7167.48,1628.78) ; 7147.8,1681.99 cw(c7147.8,1667.89) 7157.77,1677.86 cw(c7167.74,1687.83) 7153.64,1687.83 ; 7147.8,1687.83 v2(7167.48,1668.15) ; 7147.8,1721.36 cw(c7147.8,1707.26) 7157.77,1717.23 cw(c7167.74,1727.2) 7153.64,1727.2 ; 7147.8,1727.2 v2(7167.48,1707.52) ; 7147.8,1760.73 cw(c7147.8,1746.63) 7157.77,1756.6 cw(c7167.74,1766.57) 7153.64,1766.57 ; 7147.8,1766.57 v2(7167.48,1746.89) ; 7147.8,1800.1 cw(c7147.8,1786) 7157.77,1795.97 cw(c7167.74,1805.94) 7153.64,1805.94 ; 7147.8,1805.94 v2(7167.48,1786.26) ; 7147.8,1839.47 cw(c7147.8,1825.37) 7157.77,1835.34 cw(c7167.74,1845.31) 7153.64,1845.31 ; 7147.8,1845.31 v2(7167.48,1825.63) ; 7147.8,1884.68 v2(7167.48,1904.37) ; 7147.8,1890.53 ccw(c7147.8,1904.63) 7157.77,1894.66 ccw(c7167.74,1884.68) 7153.64,1884.68 ; 7147.8,1924.06 v2(7167.48,1943.74) ; 7147.8,1929.9 ccw(c7147.8,1944) 7157.77,1934.03 ccw(c7167.74,1924.06) 7153.64,1924.06 ; 7147.8,1963.43 v2(7167.48,1983.11) ; 7147.8,1969.27 ccw(c7147.8,1983.37) 7157.77,1973.4 ccw(c7167.74,1963.43) 7153.64,1963.43 ; 7147.8,2002.8 v2(7167.48,2022.48) ; 7147.8,2008.64 ccw(c7147.8,2022.74) 7157.77,2012.77 ccw(c7167.74,2002.8) 7153.64,2002.8 ; 7147.8,2042.17 v2(7167.48,2061.85) ; 7147.8,2048.01 ccw(c7147.8,2062.11) 7157.77,2052.14 ccw(c7167.74,2042.17) 7153.64,2042.17 ; v2@7158.48,1471.3 ccw(c7136.75,1471.3) 7152.12,1486.66 ccw(c7167.48,1502.03) v2@7167.48,1480.3 ; v2@7158.48,1550.04 ccw(c7136.75,1550.04) 7152.12,1565.4 ccw(c7167.48,1580.77) v2@7167.48,1559.04 ; v2@7158.48,1589.41 ccw(c7136.75,1589.41) 7152.12,1604.77 ccw(c7167.48,1620.14) v2@7167.48,1598.41 ; v2@7158.48,1628.78 ccw(c7136.75,1628.78) 7152.12,1644.14 ccw(c7167.48,1659.51) v2@7167.48,1637.78 ; v2@7158.48,1668.15 ccw(c7136.75,1668.15) 7152.12,1683.51 ccw(c7167.48,1698.88) v2@7167.48,1677.15 ; v2@7158.48,1707.52 ccw(c7136.75,1707.52) 7152.12,1722.88 ccw(c7167.48,1738.25) v2@7167.48,1716.52 ; v2@7158.48,1746.89 ccw(c7136.75,1746.89) 7152.12,1762.25 ccw(c7167.48,1777.62) v2@7167.48,1755.89 ; v2@7158.48,1786.26 ccw(c7136.75,1786.26) 7152.12,1801.62 ccw(c7167.48,1816.99) v2@7167.48,1795.26 ; v2@7158.48,1825.63 ccw(c7136.75,1825.63) 7152.12,1840.99 ccw(c7167.48,1856.36) v2@7167.48,1834.63 ; v2@7158.48,1904.37 cw(c7136.75,1904.37) 7152.12,1889.01 cw(c7167.48,1873.64) v2@7167.48,1895.37 ; v2@7158.48,1943.74 cw(c7136.75,1943.74) 7152.12,1928.38 cw(c7167.48,1913.01) v2@7167.48,1934.74 ; v2@7158.48,1983.11 cw(c7136.75,1983.11) 7152.12,1967.75 cw(c7167.48,1952.38) v2@7167.48,1974.11 ; v2@7158.48,2022.48 cw(c7136.75,2022.48) 7152.12,2007.12 cw(c7167.48,1991.75) v2@7167.48,2013.48 ; v2@7158.48,2061.85 cw(c7136.75,2061.85) 7152.12,2046.49 cw(c7167.48,2031.12) v2@7167.48,2052.85 ; 7187.17,1524.51 cw(c7187.17,1510.41) 7197.14,1520.38 cw(c7207.11,1530.35) 7193.01,1530.35 ; 7187.17,1530.35 v2(7206.85,1510.67) ; 7187.17,1563.88 cw(c7187.17,1549.78) 7197.14,1559.75 cw(c7207.11,1569.72) 7193.01,1569.72 ; 7187.17,1569.72 v2(7206.85,1550.04) ; 7187.17,1603.25 cw(c7187.17,1589.15) 7197.14,1599.12 cw(c7207.11,1609.09) 7193.01,1609.09 ; 7187.17,1609.09 v2(7206.85,1589.41) ; 7187.17,1642.62 cw(c7187.17,1628.52) 7197.14,1638.49 cw(c7207.11,1648.46) 7193.01,1648.46 ; 7187.17,1648.46 v2(7206.85,1628.78) ; 7187.17,1721.36 cw(c7187.17,1707.26) 7197.14,1717.23 cw(c7207.11,1727.2) 7193.01,1727.2 ; 7187.17,1727.2 v2(7206.85,1707.52) ; 7187.17,1760.73 cw(c7187.17,1746.63) 7197.14,1756.6 cw(c7207.11,1766.57) 7193.01,1766.57 ; 7187.17,1766.57 v2(7206.85,1746.89) ; 7187.17,1800.1 cw(c7187.17,1786) 7197.14,1795.97 cw(c7207.11,1805.94) 7193.01,1805.94 ; 7187.17,1805.94 v2(7206.85,1786.26) ; 7187.17,1839.47 cw(c7187.17,1825.37) 7197.14,1835.34 cw(c7207.11,1845.31) 7193.01,1845.31 ; 7187.17,1845.31 v2(7206.85,1825.63) ; v2@7197.85,1510.67 ccw(c7176.12,1510.67) 7191.49,1526.03 ccw(c7206.85,1541.4) v2@7206.85,1519.67 ; v2@7197.85,1550.04 ccw(c7176.12,1550.04) 7191.49,1565.4 ccw(c7206.85,1580.77) v2@7206.85,1559.04 ; v2@7197.85,1589.41 ccw(c7176.12,1589.41) 7191.49,1604.77 ccw(c7206.85,1620.14) v2@7206.85,1598.41 ; v2@7197.85,1628.78 ccw(c7176.12,1628.78) 7191.49,1644.14 ccw(c7206.85,1659.51) v2@7206.85,1637.78 ; v2@7197.85,1707.52 ccw(c7176.12,1707.52) 7191.49,1722.88 ccw(c7206.85,1738.25) v2@7206.85,1716.52 ; v2@7197.85,1746.89 ccw(c7176.12,1746.89) 7191.49,1762.25 ccw(c7206.85,1777.62) v2@7206.85,1755.89 ; v2@7197.85,1786.26 ccw(c7176.12,1786.26) 7191.49,1801.62 ccw(c7206.85,1816.99) v2@7206.85,1795.26 ; v2@7197.85,1825.63 ccw(c7176.12,1825.63) 7191.49,1840.99 ccw(c7206.85,1856.36) v2@7206.85,1834.63 ; 7226.54,1524.51 cw(c7226.54,1510.41) 7236.51,1520.38 cw(c7246.48,1530.35) 7232.38,1530.35 ; 7226.54,1530.35 v2(7246.22,1510.67) ; 7226.54,1563.88 cw(c7226.54,1549.78) 7236.51,1559.75 cw(c7246.48,1569.72) 7232.38,1569.72 ; 7226.54,1569.72 v2(7246.22,1550.04) ; 7226.54,1681.99 cw(c7226.54,1667.89) 7236.51,1677.86 cw(c7246.48,1687.83) 7232.38,1687.83 ; 7226.54,1687.83 v2(7246.22,1668.15) ; 7226.54,1721.36 cw(c7226.54,1707.26) 7236.51,1717.23 cw(c7246.48,1727.2) 7232.38,1727.2 ; 7226.54,1727.2 v2(7246.22,1707.52) ; 7226.54,1760.73 cw(c7226.54,1746.63) 7236.51,1756.6 cw(c7246.48,1766.57) 7232.38,1766.57 ; 7226.54,1766.57 v2(7246.22,1746.89) ; v2@7237.22,1510.67 ccw(c7215.49,1510.67) 7230.86,1526.03 ccw(c7246.22,1541.4) v2@7246.22,1519.67 ; v2@7237.22,1550.04 ccw(c7215.49,1550.04) 7230.86,1565.4 ccw(c7246.22,1580.77) v2@7246.22,1559.04 ; v2@7237.22,1668.15 ccw(c7215.49,1668.15) 7230.86,1683.51 ccw(c7246.22,1698.88) v2@7246.22,1677.15 ; v2@7237.22,1707.52 ccw(c7215.49,1707.52) 7230.86,1722.88 ccw(c7246.22,1738.25) v2@7246.22,1716.52 ; v2@7237.22,1746.89 ccw(c7215.49,1746.89) 7230.86,1762.25 ccw(c7246.22,1777.62) v2@7246.22,1755.89 ; 7265.91,1485.14 cw(c7265.91,1471.04) 7275.88,1481.01 cw(c7285.85,1490.98) 7271.75,1490.98 ; 7265.91,1490.98 v2(7285.59,1471.3) ; 7265.91,1563.88 cw(c7265.91,1549.78) 7275.88,1559.75 cw(c7285.85,1569.72) 7271.75,1569.72 ; 7265.91,1569.72 v2(7285.59,1550.04) ; 7265.91,1603.25 cw(c7265.91,1589.15) 7275.88,1599.12 cw(c7285.85,1609.09) 7271.75,1609.09 ; 7265.91,1609.09 v2(7285.59,1589.41) ; 7265.91,1642.62 cw(c7265.91,1628.52) 7275.88,1638.49 cw(c7285.85,1648.46) 7271.75,1648.46 ; 7265.91,1648.46 v2(7285.59,1628.78) ; 7265.91,1681.99 cw(c7265.91,1667.89) 7275.88,1677.86 cw(c7285.85,1687.83) 7271.75,1687.83 ; 7265.91,1687.83 v2(7285.59,1668.15) ; 7265.91,1721.36 cw(c7265.91,1707.26) 7275.88,1717.23 cw(c7285.85,1727.2) 7271.75,1727.2 ; 7265.91,1727.2 v2(7285.59,1707.52) ; 7265.91,1800.1 cw(c7265.91,1786) 7275.88,1795.97 cw(c7285.85,1805.94) 7271.75,1805.94 ; 7265.91,1805.94 v2(7285.59,1786.26) ; v2@7276.59,1471.3 ccw(c7254.86,1471.3) 7270.23,1486.66 ccw(c7285.59,1502.03) v2@7285.59,1480.3 ; v2@7276.59,1550.04 ccw(c7254.86,1550.04) 7270.23,1565.4 ccw(c7285.59,1580.77) v2@7285.59,1559.04 ; v2@7276.59,1589.41 ccw(c7254.86,1589.41) 7270.23,1604.77 ccw(c7285.59,1620.14) v2@7285.59,1598.41 ; v2@7276.59,1628.78 ccw(c7254.86,1628.78) 7270.23,1644.14 ccw(c7285.59,1659.51) v2@7285.59,1637.78 ; v2@7276.59,1668.15 ccw(c7254.86,1668.15) 7270.23,1683.51 ccw(c7285.59,1698.88) v2@7285.59,1677.15 ; v2@7276.59,1707.52 ccw(c7254.86,1707.52) 7270.23,1722.88 ccw(c7285.59,1738.25) v2@7285.59,1716.52 ; v2@7276.59,1786.26 ccw(c7254.86,1786.26) 7270.23,1801.62 ccw(c7285.59,1816.99) v2@7285.59,1795.26 ; 7305.28,1485.14 cw(c7305.28,1471.04) 7315.25,1481.01 cw(c7325.22,1490.98) 7311.12,1490.98 ; 7305.28,1490.98 v2(7324.96,1471.3) ; 7305.28,1524.51 cw(c7305.28,1510.41) 7315.25,1520.38 cw(c7325.22,1530.35) 7311.12,1530.35 ; 7305.28,1530.35 v2(7324.96,1510.67) ; 7305.28,1603.25 cw(c7305.28,1589.15) 7315.25,1599.12 cw(c7325.22,1609.09) 7311.12,1609.09 ; 7305.28,1609.09 v2(7324.96,1589.41) ; 7305.28,1642.62 cw(c7305.28,1628.52) 7315.25,1638.49 cw(c7325.22,1648.46) 7311.12,1648.46 ; 7305.28,1648.46 v2(7324.96,1628.78) ; 7305.28,1681.99 cw(c7305.28,1667.89) 7315.25,1677.86 cw(c7325.22,1687.83) 7311.12,1687.83 ; 7305.28,1687.83 v2(7324.96,1668.15) ; 7305.28,1721.36 cw(c7305.28,1707.26) 7315.25,1717.23 cw(c7325.22,1727.2) 7311.12,1727.2 ; 7305.28,1727.2 v2(7324.96,1707.52) ; v2@7315.96,1471.3 ccw(c7294.23,1471.3) 7309.6,1486.66 ccw(c7324.96,1502.03) v2@7324.96,1480.3 ; v2@7315.96,1510.67 ccw(c7294.23,1510.67) 7309.6,1526.03 ccw(c7324.96,1541.4) v2@7324.96,1519.67 ; v2@7315.96,1589.41 ccw(c7294.23,1589.41) 7309.6,1604.77 ccw(c7324.96,1620.14) v2@7324.96,1598.41 ; v2@7315.96,1628.78 ccw(c7294.23,1628.78) 7309.6,1644.14 ccw(c7324.96,1659.51) v2@7324.96,1637.78 ; v2@7315.96,1668.15 ccw(c7294.23,1668.15) 7309.6,1683.51 ccw(c7324.96,1698.88) v2@7324.96,1677.15 ; v2@7315.96,1707.52 ccw(c7294.23,1707.52) 7309.6,1722.88 ccw(c7324.96,1738.25) v2@7324.96,1716.52 ; 7344.65,1485.14 cw(c7344.65,1471.04) 7354.62,1481.01 cw(c7364.59,1490.98) 7350.49,1490.98 ; 7344.65,1490.98 v2(7364.33,1471.3) ; 7344.65,1524.51 cw(c7344.65,1510.41) 7354.62,1520.38 cw(c7364.59,1530.35) 7350.49,1530.35 ; 7344.65,1530.35 v2(7364.33,1510.67) ; 7344.65,1563.88 cw(c7344.65,1549.78) 7354.62,1559.75 cw(c7364.59,1569.72) 7350.49,1569.72 ; 7344.65,1569.72 v2(7364.33,1550.04) ; 7344.65,1603.25 cw(c7344.65,1589.15) 7354.62,1599.12 cw(c7364.59,1609.09) 7350.49,1609.09 ; 7344.65,1609.09 v2(7364.33,1589.41) ; 7344.65,1681.99 cw(c7344.65,1667.89) 7354.62,1677.86 cw(c7364.59,1687.83) 7350.49,1687.83 ; 7344.65,1687.83 v2(7364.33,1668.15) ; v2@7355.33,1471.3 ccw(c7333.6,1471.3) 7348.97,1486.66 ccw(c7364.33,1502.03) v2@7364.33,1480.3 ; v2@7355.33,1510.67 ccw(c7333.6,1510.67) 7348.97,1526.03 ccw(c7364.33,1541.4) v2@7364.33,1519.67 ; v2@7355.33,1550.04 ccw(c7333.6,1550.04) 7348.97,1565.4 ccw(c7364.33,1580.77) v2@7364.33,1559.04 ; v2@7355.33,1589.41 ccw(c7333.6,1589.41) 7348.97,1604.77 ccw(c7364.33,1620.14) v2@7364.33,1598.41 ; v2@7355.33,1668.15 ccw(c7333.6,1668.15) 7348.97,1683.51 ccw(c7364.33,1698.88) v2@7364.33,1677.15 ; 7384.02,1563.88 cw(c7384.02,1549.78) 7393.99,1559.75 cw(c7403.96,1569.72) 7389.86,1569.72 ; 7384.02,1569.72 v2(7403.7,1550.04) ; 7384.02,1603.25 cw(c7384.02,1589.15) 7393.99,1599.12 cw(c7403.96,1609.09) 7389.86,1609.09 ; 7384.02,1609.09 v2(7403.7,1589.41) ; 7384.02,1642.62 cw(c7384.02,1628.52) 7393.99,1638.49 cw(c7403.96,1648.46) 7389.86,1648.46 ; 7384.02,1648.46 v2(7403.7,1628.78) ; 7384.02,1681.99 cw(c7384.02,1667.89) 7393.99,1677.86 cw(c7403.96,1687.83) 7389.86,1687.83 ; 7384.02,1687.83 v2(7403.7,1668.15) ; v2@7394.7,1550.04 ccw(c7372.97,1550.04) 7388.34,1565.4 ccw(c7403.7,1580.77) v2@7403.7,1559.04 ; v2@7394.7,1589.41 ccw(c7372.97,1589.41) 7388.34,1604.77 ccw(c7403.7,1620.14) v2@7403.7,1598.41 ; v2@7394.7,1628.78 ccw(c7372.97,1628.78) 7388.34,1644.14 ccw(c7403.7,1659.51) v2@7403.7,1637.78 ; v2@7394.7,1668.15 ccw(c7372.97,1668.15) 7388.34,1683.51 ccw(c7403.7,1698.88) v2@7403.7,1677.15 ; v2(7692.52,4327.52) 7712.2,4347.2 ; v2@7692.52,4336.52 ccw(c7692.52,4358.25) 7707.88,4342.88 ccw(c7723.25,4327.52) v2@7701.52,4327.52 ; v2@7692.52,4633.48 cw(c7692.52,4611.75) 7707.88,4627.12 cw(c7723.25,4642.48) v2@7701.52,4642.48 ; v2(7692.52,4642.48) 7712.2,4622.8 ; 7706.2,4347.2 cw(c7691.72,4347.2) 7701.96,4336.96 cw(c7712.2,4326.72) 7712.2,4341.2 ; 7706.2,4622.8 ccw(c7691.72,4622.8) 7701.96,4633.04 ccw(c7712.2,4643.28) 7712.2,4628.8 ; v2(7731.89,4327.52) 7751.58,4347.2 ; v2@7731.89,4336.52 ccw(c7731.89,4358.25) 7747.25,4342.88 ccw(c7762.62,4327.52) v2@7740.89,4327.52 ; v2@7731.89,4633.48 cw(c7731.89,4611.75) 7747.25,4627.12 cw(c7762.62,4642.48) v2@7740.89,4642.48 ; v2(7731.89,4642.48) 7751.58,4622.8 ; 7745.58,4347.2 cw(c7731.09,4347.2) 7741.33,4336.96 cw(c7751.58,4326.72) 7751.58,4341.2 ; 7745.58,4622.8 ccw(c7731.09,4622.8) 7741.33,4633.04 ccw(c7751.58,4643.28) 7751.58,4628.8 ; v2(7771.26,4327.52) 7790.95,4347.2 ; v2@7771.26,4336.52 ccw(c7771.26,4358.25) 7786.62,4342.88 ccw(c7801.99,4327.52) v2@7780.26,4327.52 ; 7784.95,4347.2 cw(c7770.46,4347.2) 7780.7,4336.96 cw(c7790.95,4326.72) 7790.95,4341.2 ; v2@7810.63,4633.48 cw(c7810.63,4611.75) 7825.99,4627.12 cw(c7841.36,4642.48) v2@7819.63,4642.48 ; v2(7810.63,4642.48) 7830.32,4622.8 ; 7824.32,4622.8 ccw(c7809.83,4622.8) 7820.07,4633.04 ccw(c7830.32,4643.28) 7830.32,4628.8 ; 7869.69,4622.8 v2(7889.37,4642.48) ; 7869.69,4628.8 ccw(c7869.69,4643.28) 7879.93,4633.04 ccw(c7890.17,4622.8) 7875.69,4622.8 ; v2@7880.37,4642.48 cw(c7858.64,4642.48) 7874.01,4627.12 cw(c7889.37,4611.75) v2@7889.37,4633.48 ; 7909.06,4622.8 v2(7928.74,4642.48) ; 7909.06,4628.8 ccw(c7909.06,4643.28) 7919.3,4633.04 ccw(c7929.54,4622.8) 7915.06,4622.8 ; v2@7919.74,4642.48 cw(c7898.01,4642.48) 7913.38,4627.12 cw(c7928.74,4611.75) v2@7928.74,4633.48 ; 7948.43,4504.69 v2(7968.11,4524.37) ; 7948.43,4510.69 ccw(c7948.43,4525.17) 7958.67,4514.93 ccw(c7968.91,4504.69) 7954.43,4504.69 ; 7948.43,4622.8 v2(7968.11,4642.48) ; 7948.43,4628.8 ccw(c7948.43,4643.28) 7958.67,4633.04 ccw(c7968.91,4622.8) 7954.43,4622.8 ; v2@7959.11,4524.37 cw(c7937.38,4524.37) 7952.75,4509.01 cw(c7968.11,4493.64) v2@7968.11,4515.37 ; v2@7959.11,4642.48 cw(c7937.38,4642.48) 7952.75,4627.12 cw(c7968.11,4611.75) v2@7968.11,4633.48 ; 7987.8,4341.2 cw(c7987.8,4326.72) 7998.04,4336.96 cw(c8008.28,4347.2) 7993.8,4347.2 ; 7987.8,4347.2 v2(8007.48,4327.52) ; 7987.8,4622.8 v2(8007.48,4642.48) ; 7987.8,4628.8 ccw(c7987.8,4643.28) 7998.04,4633.04 ccw(c8008.28,4622.8) 7993.8,4622.8 ; v2@7998.48,4327.52 ccw(c7976.75,4327.52) 7992.12,4342.88 ccw(c8007.48,4358.25) v2@8007.48,4336.52 ; v2@7998.48,4642.48 cw(c7976.75,4642.48) 7992.12,4627.12 cw(c8007.48,4611.75) v2@8007.48,4633.48
  MidLayer1 w4: 4870,3859.53 4918.62,3859.53 4938.04,3859.53 4998.23,3859.53 5002.99,3859.53 ccw(c5003.16,3892.66) 5020.81,3864.62 ; 4870,3875.04 4918.62,3875.04 4938.04,3875.04 v3(4996.3,3875.04) ; 4870,3914.41 4918.62,3914.41 4938.04,3914.41 v3(4996.3,3914.41) ; v3@4991.11,3869.85 ccw(c4978.57,3857.31) 4978.57,3875.04 ccw(c4978.57,3892.77) v3@4991.11,3880.23 ; v3@4991.11,3909.22 ccw(c4978.57,3896.68) 4978.57,3914.41 ccw(c4978.57,3932.14) v3@4991.11,3919.6 ; v3@5028.28,3876.34 cw(c5010.45,3879.49) 5020.84,3864.65 cw(c5031.22,3849.82) v3@5034.37,3867.65 ; v3@5030.48,3791.11 cw(c5017.94,3778.57) 5035.67,3778.57 cw(c5053.4,3778.57) v3@5040.86,3791.11 ; v3@5030.48,4588.89 ccw(c5017.94,4601.43) 5035.67,4601.43 ccw(c5053.4,4601.43) v3@5040.86,4588.89 ; 5035.67,3670 5035.67,3718.62 5035.67,3738.04 v3(5035.67,3796.3) ; v3(5035.67,4583.7) 5035.67,4641.96 5035.67,4661.38 5035.67,4710 ; 5059.53,4710 5059.53,4661.38 5059.53,4577.01 ccw(c5092.66,4576.84) 5064.62,4559.19 ; v3@5067.65,4545.63 ccw(c5049.82,4548.78) 5064.65,4559.16 ccw(c5079.49,4569.55) v3@5076.34,4551.72 ; 5129.92,3670 5129.92,3718.62 5129.92,3738.04 5129.92,3812.16 ; 5129.92,3798.23 5129.92,3812.16 ; v3@5146.31,3874.39 cw(c5128.27,3872.81) 5142.14,3861.17 ; v3@5154.43,3867.57 ccw(c5156.01,3849.53) 5142.14,3861.17 ; 5169.29,4581.77 5169.29,4567.84 ; 5169.29,4710 5169.29,4661.38 5169.29,4641.96 5169.29,4567.84 ; 5177.64,4710 5177.64,4661.38 5177.64,4567.84 ccw(c5191.69,4567.84) 5181.76,4557.91 ; v3@5185.68,4505.61 ccw(c5167.64,4507.19) 5181.51,4518.83 ; v3@5185.68,4544.98 ccw(c5167.64,4546.56) 5181.51,4558.2 ccw(c5195.38,4569.84) v3@5193.8,4551.8 ; v3@5193.8,4512.43 cw(c5195.38,4530.47) 5181.51,4518.83 ; 5208.66,4581.77 5208.66,4567.84 ; 5208.66,4710 5208.66,4661.38 5208.66,4641.96 5208.66,4567.84 ; v3@5225.05,4505.61 ccw(c5207.01,4507.19) 5220.88,4518.83 ; v3@5233.17,4512.43 cw(c5234.75,4530.47) 5220.88,4518.83 ; 5256.38,4710 5256.38,4661.38 5256.38,4641.96 5256.38,4581.77 5256.38,4567.84 ccw(c5270.43,4567.84) 5260.5,4557.91 ; v3@5264.42,4544.98 ccw(c5246.38,4546.56) 5260.25,4558.2 ccw(c5274.12,4569.84) v3@5272.54,4551.8 ; 5295.75,4581.77 5295.75,4567.84 ; 5295.75,4720 5295.75,4710 5295.75,4661.38 5295.75,4567.84 ; 5299.87,4557.91 cw(c5309.8,4567.84) 5295.75,4567.84 ; v3@5303.79,4544.98 ccw(c5285.75,4546.56) 5299.62,4558.2 ccw(c5313.49,4569.84) v3@5311.91,4551.8 ; v3@5305.96,4589 ccw(c5293.15,4601.81) 5311.26,4601.81 ccw(c5329.37,4601.81) v3@5316.56,4589 ; v3@5306.07,4588.89 ccw(c5293.53,4601.43) 5311.26,4601.43 ccw(c5328.99,4601.43) v3@5316.45,4588.89 ; v3(5311.26,4583.7) 5311.26,4710 ; v3@5424.18,4588.89 ccw(c5411.64,4601.43) 5429.37,4601.43 ccw(c5447.1,4601.43) v3@5434.56,4588.89 ; v3(5429.37,4583.7) 5429.37,4661.38 5429.37,4710 ; v3@5463.44,4589 ccw(c5450.63,4601.81) 5468.74,4601.81 ccw(c5486.85,4601.81) v3@5474.04,4589 ; v3@5463.55,4588.89 ccw(c5451.01,4601.43) 5468.74,4601.43 ccw(c5486.47,4601.43) v3@5473.93,4588.89 ; v3(5468.74,4583.7) 5468.74,4710 ; v3@5586.2,4512.43 ccw(c5584.62,4530.47) 5598.49,4518.83 ; v3@5586.2,4551.8 ccw(c5584.62,4569.84) 5598.49,4558.2 ccw(c5612.36,4546.56) v3@5594.32,4544.98 ; v3@5594.32,4505.61 cw(c5612.36,4507.19) 5598.49,4518.83 ; 5598.24,4557.91 ccw(c5588.31,4567.84) 5602.36,4567.84 5602.36,4661.38 5602.36,4710 ; 5610.71,4581.77 5610.71,4567.84 ; 5610.71,4710 5610.71,4661.38 5610.71,4641.96 5610.71,4567.84 ; v3@5620.92,4589 ccw(c5608.11,4601.81) 5626.22,4601.81 ccw(c5644.33,4601.81) v3@5631.52,4589 ; v3@5621.03,4588.89 ccw(c5608.49,4601.43) 5626.22,4601.43 ccw(c5643.95,4601.43) v3@5631.41,4588.89 ; v3(5626.22,4583.7) 5626.22,4661.38 5626.22,4710 ; v3@5664.94,4551.8 ccw(c5663.36,4569.84) 5677.23,4558.2 ccw(c5691.1,4546.56) v3@5673.06,4544.98 ; 5676.99,4557.91 ccw(c5667.05,4567.84) 5681.1,4567.84 5681.1,4661.38 5681.1,4710 ; v3@5739.14,3791.11 cw(c5726.6,3778.57) 5744.33,3778.57 cw(c5762.06,3778.57) v3@5749.52,3791.11 ; 5744.33,3670 5744.33,3718.62 5744.33,3738.04 v3(5744.33,3796.3) ; v3(5783.7,4111.26) 5841.96,4111.26 5861.38,4111.26 5910,4111.26 ; v3(5783.7,4229.37) 5841.96,4229.37 5861.38,4229.37 5910,4229.37 ; v3(5783.7,4308.11) 5841.96,4308.11 5861.38,4308.11 5910,4308.11 ; v3(5783.7,4426.22) 5841.96,4426.22 5861.38,4426.22 5910,4426.22 ; v3@5788.89,4106.07 cw(c5801.43,4093.53) 5801.43,4111.26 cw(c5801.43,4128.99) v3@5788.89,4116.45 ; v3@5788.89,4224.18 cw(c5801.43,4211.64) 5801.43,4229.37 cw(c5801.43,4247.1) v3@5788.89,4234.56 ; v3@5788.89,4302.92 cw(c5801.43,4290.38) 5801.43,4308.11 cw(c5801.43,4325.84) v3@5788.89,4313.3 ; v3@5788.89,4421.03 cw(c5801.43,4408.49) 5801.43,4426.22 cw(c5801.43,4443.95) v3@5788.89,4431.41 ; v3@5789,4105.96 cw(c5801.81,4093.15) 5801.81,4111.26 cw(c5801.81,4129.37) v3@5789,4116.56 ; v3@5789,4302.81 cw(c5801.81,4290) 5801.81,4308.11 cw(c5801.81,4326.22) v3@5789,4313.41 ; v3@5789,4420.92 cw(c5801.81,4408.11) 5801.81,4426.22 cw(c5801.81,4444.33) v3@5789,4431.52 ; 4978.19,3875.04 ccw(c4978.19,3893.15) 4991,3880.34 cw(c4978.19,3893.15) 4978.19,3875.04 ; 4978.19,3875.04 cw(c4978.19,3856.93) 4991,3869.74 ccw(c4978.19,3856.93) 4978.19,3875.04 ; 4978.19,3914.41 cw(c4978.19,3896.3) 4991,3909.11 ccw(c4978.19,3896.3) 4978.19,3914.41 ; 4978.19,3914.41 ccw(c4978.19,3932.52) 4991,3919.71 cw(c4978.19,3932.52) 4978.19,3914.41 ; 5035.67,3778.19 cw(c5053.78,3778.19) 5040.97,3791 ccw(c5053.78,3778.19) 5035.67,3778.19 ; 5035.67,3778.19 ccw(c5017.56,3778.19) 5030.37,3791 cw(c5017.56,3778.19) 5035.67,3778.19 ; 5035.67,4601.81 ccw(c5053.78,4601.81) 5040.97,4589 cw(c5053.78,4601.81) 5035.67,4601.81 ; 5035.67,4601.81 cw(c5017.56,4601.81) 5030.37,4589 ccw(c5017.56,4601.81) 5035.67,4601.81 ; 5129.92,3812.16 5129.92,3831.66 cw(c5171.65,3831.66) 5142.14,3861.17 ; 5169.29,4567.84 5169.29,4548.34 ccw(c5211.02,4548.34) 5181.51,4518.83 ; 5208.66,4567.84 5208.66,4548.34 ccw(c5250.39,4548.34) 5220.88,4518.83 ; 5429.37,4601.81 cw(c5411.26,4601.81) 5424.07,4589 ccw(c5411.26,4601.81) 5429.37,4601.81 ; 5429.37,4601.81 ccw(c5447.48,4601.81) 5434.67,4589 cw(c5447.48,4601.81) 5429.37,4601.81 ; 5598.49,4518.83 ccw(c5568.98,4548.34) 5610.71,4548.34 5610.71,4567.84 ; 5744.33,3778.19 cw(c5762.44,3778.19) 5749.63,3791 ccw(c5762.44,3778.19) 5744.33,3778.19 ; 5744.33,3778.19 ccw(c5726.22,3778.19) 5739.03,3791 cw(c5726.22,3778.19) 5744.33,3778.19 ; 5801.81,4229.37 cw(c5801.81,4247.48) 5789,4234.67 ccw(c5801.81,4247.48) 5801.81,4229.37 ; 5801.81,4229.37 ccw(c5801.81,4211.26) 5789,4224.07 cw(c5801.81,4211.26) 5801.81,4229.37
  MidLayer2 w4: 5256.38,3670 5256.38,3797.36 5256.38,3890.9 ; 5256.38,3876.97 5256.38,3890.9 ; 5256.38,4503.03 5256.38,4489.1 ; 5256.38,4710 5256.38,4582.64 5256.38,4489.1 ; 5260.5,3900.83 ccw(c5270.43,3890.9) 5256.38,3890.9 ; 5260.5,4479.17 cw(c5270.43,4489.1) 5256.38,4489.1 ; v3@5264.42,3913.76 cw(c5246.38,3912.18) 5260.25,3900.54 cw(c5274.12,3888.9) v3@5272.54,3906.94 ; v3@5264.42,4466.24 ccw(c5246.38,4467.82) 5260.25,4479.46 ccw(c5274.12,4491.1) v3@5272.54,4473.06 ; 5326.77,4710 5326.77,4582.64 5326.77,4563.22 5326.77,4489.1 5326.77,4469.6 ccw(c5368.5,4469.6) 5338.99,4440.09 ; v3@5343.16,4426.87 ccw(c5325.12,4428.45) 5338.99,4440.09 ; v3@5351.28,4433.69 cw(c5352.86,4451.73) 5338.99,4440.09 ; v3@5428.72,4473.06 ccw(c5427.14,4491.1) 5441.01,4479.46 ccw(c5454.88,4467.82) v3@5436.84,4466.24 ; 5440.76,4479.17 ccw(c5430.83,4489.1) 5444.88,4489.1 5444.88,4582.64 5444.88,4710 ; v3@5507.46,3906.94 cw(c5505.88,3888.9) 5519.75,3900.54 cw(c5533.62,3912.18) v3@5515.58,3913.76 ; v3@5507.46,4473.06 ccw(c5505.88,4491.1) 5519.75,4479.46 ccw(c5533.62,4467.82) v3@5515.58,4466.24 ; 5519.5,3900.83 cw(c5509.57,3890.9) 5523.62,3890.9 ; 5519.5,4479.17 ccw(c5509.57,4489.1) 5523.62,4489.1 ; 5523.62,3670 5523.62,3797.36 5523.62,3890.9 ; 5523.62,3876.97 5523.62,3890.9 ; 5523.62,4503.03 5523.62,4489.1 ; 5523.62,4710 5523.62,4582.64 5523.62,4489.1 ; v3@5585.55,3946.39 cw(c5582.4,3928.56) 5597.24,3938.95 ; v3@5585.55,4433.61 ccw(c5582.4,4451.44) 5597.24,4441.05 ; v3@5586.2,3906.94 cw(c5584.62,3888.9) 5598.49,3900.54 cw(c5612.36,3912.18) v3@5594.32,3913.76 ; v3@5586.2,4473.06 ccw(c5584.62,4491.1) 5598.49,4479.46 ccw(c5612.36,4467.82) v3@5594.32,4466.24 ; v3@5594.24,3952.48 ccw(c5612.07,3949.33) 5597.24,3938.95 ; v3@5594.24,4427.52 cw(c5612.07,4430.67) 5597.24,4441.05 ; 5598.24,3900.83 cw(c5588.31,3890.9) 5602.36,3890.9 ; 5598.24,4479.17 ccw(c5588.31,4489.1) 5602.36,4489.1 ; 5602.36,3670 5602.36,3797.36 5602.36,3890.9 ; 5602.36,3876.97 5602.36,3890.9 ; 5602.36,4503.03 5602.36,4489.1 ; 5602.36,4710 5602.36,4582.64 5602.36,4489.1 ; 5610.71,3670 5610.71,3739.1 ; 5610.71,3680.84 5610.71,3739.1 ; 5610.71,4699.16 5610.71,4640.9 ; 5610.71,4710 5610.71,4640.9 ; 5597.24,3938.95 5604.32,3930.37 cw(c5586.94,3914.15) 5610.71,3914.15 5610.71,3890.9 5610.71,3816.78 5610.71,3797.36 5610.71,3739.1 ; 5597.24,4441.05 5604.32,4449.63 ccw(c5586.94,4465.85) 5610.71,4465.85 5610.71,4489.1 5610.71,4563.22 5610.71,4582.64 5610.71,4640.9
  Bottom Layer w4: 5051.27,3670 5051.27,3679.78 5051.27,3738.04 5051.27,3796.3 cw(c5075.04,3796.3) 5075.04,3820.07 ccw(c5075.04,3835.67) 5090.64,3835.67 cw(c5114.41,3835.67) 5114.41,3859.44 ccw(c5114.41,3875.04) 5130.01,3875.04 cw(c5153.78,3875.04) 5136.97,3891.85 5143.39,3899.58 ; v3@5146.39,3913.11 cw(c5128.56,3909.96) 5143.39,3899.58 ; v3@5155.08,3907.02 ccw(c5158.23,3889.19) 5143.39,3899.58 ; 5217.01,4710 5217.01,4678.68 5217.01,4620.42 5217.01,4562.16 5217.01,4503.9 5217.01,4484.48 5217.01,4424.29 5217.01,4419.53 ccw(c5250.14,4419.36) 5222.1,4401.71 ; v3@5225.13,4388.15 ccw(c5207.3,4391.3) 5222.13,4401.68 ccw(c5236.97,4412.07) v3@5233.82,4394.24 ; 5335.12,4710 5335.12,4678.68 5335.12,4620.42 5335.12,4562.16 5335.12,4503.9 5335.12,4484.48 5335.12,4424.29 5335.12,4410.36 ccw(c5349.17,4410.36) 5339.24,4400.43 ; v3@5343.16,4387.5 ccw(c5325.12,4389.08) 5338.99,4400.72 ccw(c5352.86,4412.36) v3@5351.28,4394.32 ; v3@5468.09,4394.32 ccw(c5466.51,4412.36) 5480.38,4400.72 ccw(c5494.25,4389.08) v3@5476.21,4387.5 ; 5480.13,4400.43 ccw(c5470.2,4410.36) 5484.25,4410.36 5484.25,4424.29 5484.25,4484.48 5484.25,4503.9 5484.25,4562.16 5484.25,4620.42 5484.25,4678.68 5484.25,4710 ; v3@5546.18,4394.24 ccw(c5543.03,4412.07) 5557.87,4401.68 ccw(c5572.7,4391.3) v3@5554.87,4388.15 ; 5557.9,4401.71 ccw(c5529.86,4419.36) 5562.99,4419.53 5562.99,4424.29 5562.99,4484.48 5562.99,4503.9 5562.99,4562.16 5562.99,4620.42 5562.99,4678.68 5562.99,4710 ; v3@5624.92,3907.02 cw(c5621.77,3889.19) 5636.61,3899.58 ; v3@5633.61,3913.11 ccw(c5651.44,3909.96) 5636.61,3899.58 ; 5728.73,3670 5728.73,3679.78 5728.73,3738.04 5728.73,3796.3 ccw(c5704.96,3796.3) 5704.96,3820.07 cw(c5704.96,3835.67) 5689.36,3835.67 ccw(c5665.59,3835.67) 5665.59,3859.44 cw(c5665.59,3875.04) 5649.99,3875.04 ccw(c5626.22,3875.04) 5643.03,3891.85 5636.61,3899.58

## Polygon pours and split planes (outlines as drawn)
GND on Top Layer "TOP POLY POUR" (solid, remove dead copper, pour order 1012): 369 vertices, not listed, extent -923.8,-15.55 8603.76,6914.22
1V8 on Top Layer "Bottom Layer-No Net" (solid, remove dead copper, pour order 1002): 2567.37,1400 2070,1400 2070,2300 2074.45,2304.02 3120,2304.02 3120,1400
2V5 on Top Layer "Bottom Layer-No Net" (solid, remove dead copper, pour order 1001): 1482.37,1400 985,1400 985,2300 989.45,2304.02 2035,2304.02 2035,1400
3V3 on Top Layer "Bottom Layer-No Net" (solid, remove dead copper, pour order 1000): 397.37,1400 -100,1400 -100,2300 -95.55,2304.02 950,2304.02 950,1400
GND on MidLayer1 "Keep-Out Layer-No Net" (solid, remove dead copper, pour order 1013): 369 vertices, not listed, extent -923.8,-15.55 8603.76,6914.22
1V8 on MidLayer1 "Bottom Layer-No Net" (solid, remove dead copper, pour order 1005): 2567.37,1400 2070,1400 2070,2300 2074.45,2304.02 3120,2304.02 3120,1400
2V5 on MidLayer1 "Bottom Layer-No Net" (solid, remove dead copper, pour order 1004): 1482.37,1400 985,1400 985,2300 989.45,2304.02 2035,2304.02 2035,1400
3V3 on MidLayer1 "Bottom Layer-No Net" (solid, remove dead copper, pour order 1003): 397.37,1400 -100,1400 -100,2300 -95.55,2304.02 950,2304.02 950,1400
GND on MidLayer2 "Keep-Out Layer-No Net" (solid, remove dead copper, pour order 1014): 369 vertices, not listed, extent -923.8,-15.55 8603.76,6914.22
1V8 on MidLayer2 "Bottom Layer-No Net" (solid, remove dead copper, pour order 1008): 2567.37,1400 2070,1400 2070,2300 2074.45,2304.02 3120,2304.02 3120,1400
2V5 on MidLayer2 "Bottom Layer-No Net" (solid, remove dead copper, pour order 1007): 1482.37,1400 985,1400 985,2300 989.45,2304.02 2035,2304.02 2035,1400
3V3 on MidLayer2 "Bottom Layer-No Net" (solid, remove dead copper, pour order 1006): 397.37,1400 -100,1400 -100,2300 -95.55,2304.02 950,2304.02 950,1400
GND on Bottom Layer "Keep-Out Layer-No Net" (solid, remove dead copper, pour order 1015): 369 vertices, not listed, extent -923.8,-15.55 8603.76,6914.22
1V8 on Bottom Layer "Bottom Layer-No Net" (solid, remove dead copper, pour order 1011): 2567.37,1400 2070,1400 2070,2300 2074.45,2304.02 3120,2304.02 3120,1400
2V5 on Bottom Layer "Bottom Layer-No Net" (solid, remove dead copper, pour order 1010): 1482.37,1400 985,1400 985,2300 989.45,2304.02 2035,2304.02 2035,1400
3V3 on Bottom Layer "Bottom Layer-No Net" (solid, pour order 1009): 397.37,1400 -100,1400 -100,2300 -95.55,2304.02 950,2304.02 950,1400
no net on Top Overlay "PIN 1 Top Overlay" (solid, pour order 1000): 4875.48,4704.78 4844.59,4755.17 4825.09,4735.67
no net on Top Overlay "PIN 1 Top Overlay" (solid, pour order 1000): 5580.22,2305.48 5529.83,2274.59 5549.33,2255.09
no net on Top Overlay "PIN 1 Top Overlay" (solid, pour order 1000): 7409.78,2264.52 7460.17,2295.41 7440.67,2314.91
GND on GND+SHIELD (split plane): 1648 vertices, not listed, extent -525.07,83.3 8583.66,6669.97
SHIELD on GND+SHIELD (split plane): 1713 vertices, not listed, extent -903.7,4.55 7675.65,6894.13
1V2 on GND+SHIELD (split plane): 1264 vertices, not listed, extent 955.03,1326.29 7734.36,5073.71
AUGND on GND+SHIELD (split plane): 151 vertices, not listed, extent -521.1,3180.3 104.71,5764.7
2V5 on GND+SHIELD (split plane): 381 vertices, not listed, extent 740.09,1255 4119.97,3444.28
AUGND on GND+SHIELD (split plane): 80 vertices, not listed, extent -424.96,2235.04 219.96,2999.96
1V8 on GND+SHIELD (split plane): 204 vertices, not listed, extent 892.53,1435.03 2995.52,3162.48
AGND on GND+SHIELD (split plane): 112 vertices, not listed, extent 114.84,5202.44 1289.74,5930.69
AGND on GND+SHIELD (split plane): 112 vertices, not listed, extent 1560.87,5202.44 2735.82,5930.69
3V3 on P2 - 3V3+5V0 (split plane): 2549 vertices, not listed, extent -503.71,4.55 8583.66,6444.96
5V0 on P2 - 3V3+5V0 (split plane): 3290 vertices, not listed, extent -903.7,4.55 8583.66,6894.13
AUGND on P2 - 3V3+5V0 (split plane): 68 vertices, not listed, extent 21.5,4.55 2460.2,495.06
+B on P2 - 3V3+5V0 (split plane): 238 vertices, not listed, extent 6924.35,5223.81 7897.45,6444.96
GND on P2 - 3V3+5V0 (split plane): 893 vertices, not listed, extent 4925.73,3725.73 5854.27,4654.27
GND on P2 - 3V3+5V0 (split plane): 243 vertices, not listed, extent 6799.72,1733.46 7181.43,1996.54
